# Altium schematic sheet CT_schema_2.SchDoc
size 276 x 169 mm
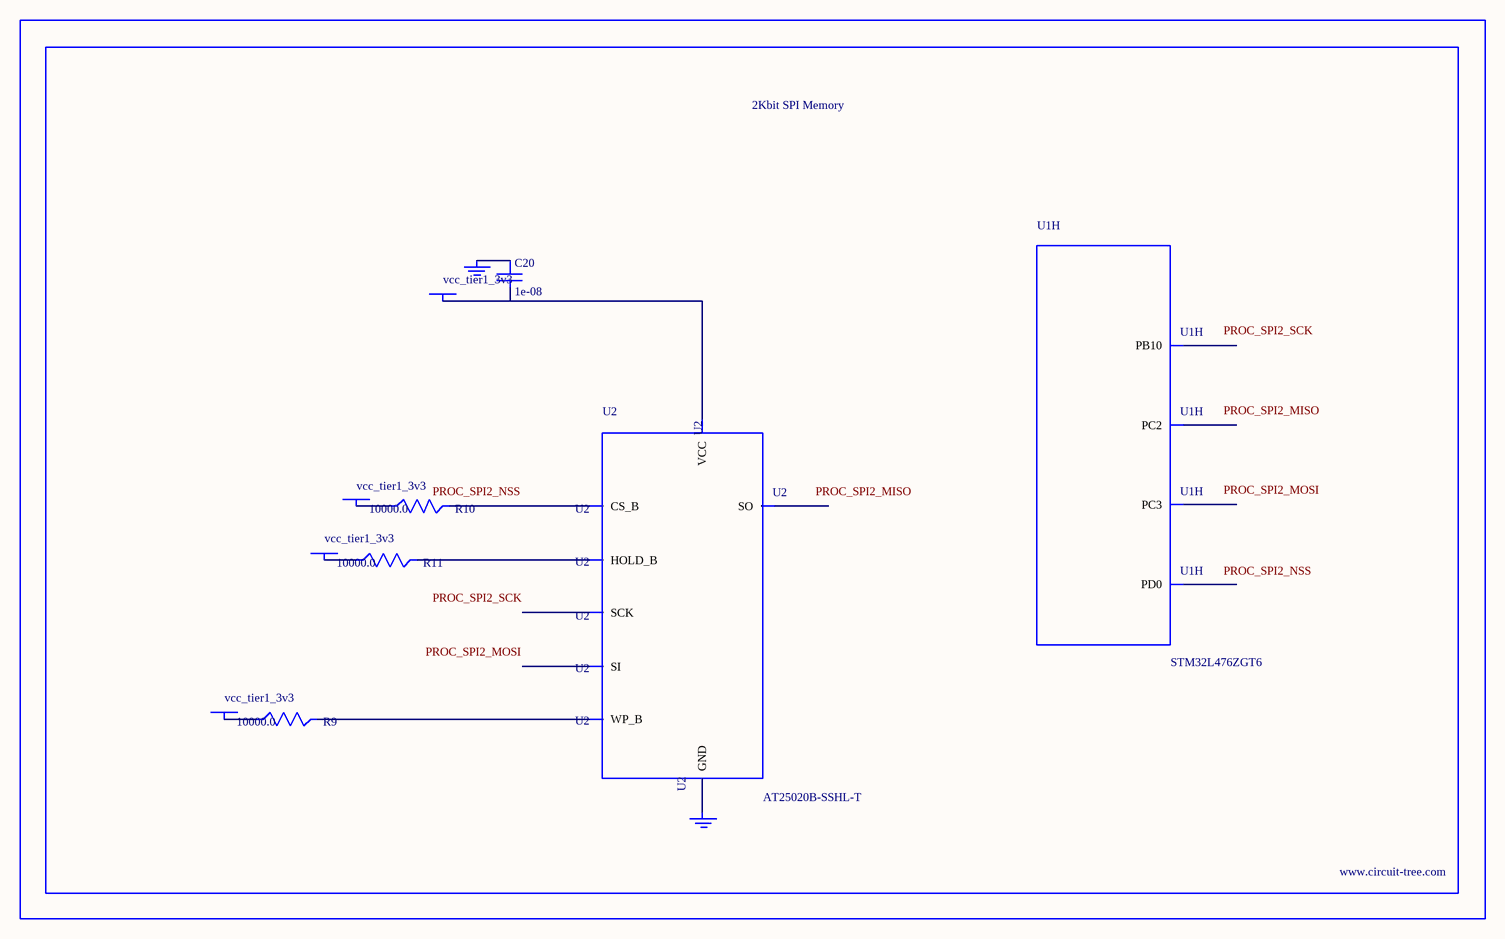
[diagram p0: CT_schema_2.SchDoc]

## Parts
BORDER1  (no value)
C20  1e-08  [C0402]
GND_INSTANCE_1_0  (no value)
GND_INSTANCE_1_1  (no value)
POWER_INSTANCE_1_0  vcc_tier1_3v3
POWER_INSTANCE_1_1  vcc_tier1_3v3
POWER_INSTANCE_1_2  vcc_tier1_3v3
POWER_INSTANCE_1_3  vcc_tier1_3v3
R9  10000.0  [R0603]
R10  10000.0  [R0603]
R11  10000.0  [R0603]
U1  STM32L476ZGT6  [LQFP144]  (part H of 13)
U2  AT25020B-SSHL-T  [SOIC-8]

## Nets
NetC20_1: C20.1 GND_INSTANCE_1_0.0(GND)
NetC20_2: C20.2 POWER_INSTANCE_1_3.0(PWR) U2.8(VCC)
NetGND_INSTANCE_1_1_0: GND_INSTANCE_1_1.0(GND) U2.4(GND)
NetPOWER_INSTANCE_1_0_0: POWER_INSTANCE_1_0.0(PWR) R10.1
NetPOWER_INSTANCE_1_1_0: POWER_INSTANCE_1_1.0(PWR) R9.1
NetPOWER_INSTANCE_1_2_0: POWER_INSTANCE_1_2.0(PWR) R11.1
NetR9_2: R9.2 U2.3(WP_B)
NetR10_2: R10.2 U2.1(CS_B)
NetR11_2: R11.2 U2.7(HOLD_B)

Not connected (* = marked no-connect by the designer): U1 28(PC2) 29(PC3) 69(PB10) 114(PD0); U2 2(SO) 5(SI) 6(SCK)

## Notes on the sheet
- Labels drawn without touching a wire or pin: PROC_SPI2_MISO, PROC_SPI2_MOSI, PROC_SPI2_NSS, PROC_SPI2_SCK

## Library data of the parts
BORDER1 = BORDER_PAGE1
C20 = C0402C103K3RAC
GND_INSTANCE_1_0 GND_INSTANCE_1_1 = GND
POWER_INSTANCE_1_0-POWER_INSTANCE_1_3 = PWR
R9-R11 = RC0603JR-0710KL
